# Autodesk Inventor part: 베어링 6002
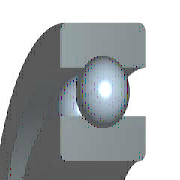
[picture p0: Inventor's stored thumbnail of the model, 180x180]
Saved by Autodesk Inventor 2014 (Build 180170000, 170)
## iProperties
IsCustomPart: 0
Created: 2015-10
Part Number: 베어링 6002
Material: 강, 연강
Description: 깊은 그루브 볼 베어링
Document SubType Name: Modeling
Standard: KS B 2023
Designer: mdu
Standards Organization: KS
Language: ko-KR
Size Designation: 6002 - 15 x 32 x 9
Categories: <MemberInstance><Categories><Category DisplayName="샤프트 부품" InternalName="7f7aeb1f-a693-4053-b835-cee3144e0d98" Mnemonic="SHFT"><Category DisplayName="베어링" Inter
Density: 1 g/cm^3
Appearance: 강철
Author: mdu
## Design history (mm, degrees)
sketch "스케치" dims "d0" = 4.42 (= -0.26 x WD + 0.26 x BD)
  geometry: L1 (2.29, 11.75)-(6.71, 11.75); L2 (4.5, 11.75)-(4.5, 9.54); L3 (4.5, 11.75)-(4.5, 13.96); L4 (2.858, 10.271)-(0, 10.271); L5 (0, 7.5)-(9, 7.5); L6 (2.858, 13.229)-(0, 13.229); L7 (0, 16)-(9, 16); L8 (9, 7.5)-(9, 10.271); L9 (6.142, 10.271)-(9, 10.271); L10 (6.142, 13.229)-(9, 13.229); L11 (9, 16)-(9, 13.229); L12 (-1.4, 0)-(8.4, 0) reference; L13 (0, -0.3)-(0, 5.3) reference
  constraints: 22 end point, 4 point on line, 2 collinear, 2 perpendicular, 2 symmetric about line, 1 midpoint, 1 parallel, 14 other
  dimensions: "d9" = 15 diameter of L5 L12 (= WD); "d11" = 32 diameter of L7 L12 (= BD); "d12" = 9 distance between parallel lines of L8 L13 (= KB); "d13" = 20.542 diameter of L9 L12 (= 0.326 x BD + 0.674 x WD)
revolve "본체" stored, may be unused: angle "d6" = 90 deg
revolve "볼" stored, may be unused: angle "d7" = 90 deg
pattern_circular "IDS_ARRAYBALL[SIMPL:T]" dims angle "d3" = 360 deg
body "Solid1"
fillet "모깎기1" dims "d1" = 0.3 (= KRS)
other parameters: "WD" = 15 [user parameter; used in 5 equation terms], "BD" = 32 [user parameter; used in 5 equation terms], "KB" = 9 [user parameter; used in 1 equation term], "KRS" = 0.3 [user parameter; used in 1 equation term], "d4" = 0, "d5" = 0, "d8" = 0, "d14" = 0, "d15" = 0, "BBA" = 0 [user parameter], "BC0" = 2850000 [user parameter], "BC" = 5590000 [user parameter], "BR" = 16 (= 0.5 x BD) [user parameter], "WR" = 7.5 (= 0.5 x WD) [user parameter]
